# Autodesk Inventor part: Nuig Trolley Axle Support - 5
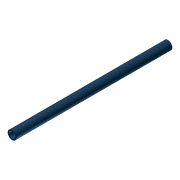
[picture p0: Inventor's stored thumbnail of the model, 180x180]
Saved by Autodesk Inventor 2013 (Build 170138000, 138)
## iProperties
Shininess: 64.0
Length Units: 11269
Angle Units: 11279
Time Units: 11290
Mass Units: 11286
Length Display Precision: 3
Angle Display Precision: 2
Created: 2002-08
Part Number: Nuig Trolley Axle Support - 5
Document SubType Name: Modeling
Designer: kalamea
Density: 1 g/cm^3
Material: Generic
Mass: 100.65 g
Surface Area: 638.451 cm^2
Volume: 100.65 cm^3
Density: 0.0
Volumn: 0.0
Area: 0.0
PropertySet Name: Model Information
Control State: 0
Master: False
Checked Out: False
DRAWING NUMBER: ME04-2007-PT
Author: kalamea
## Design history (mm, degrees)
sketch "Sketch1"
  geometry: C1 r 12.7 at (0, 0); C2 r 9.525 at (0, 0); 1 further point
  constraints: 2 centre point, 2 coincident
  dimensions: "d0" = 19.05 diameter of C2; "d1" = 25.4 diameter of C1
extrude "Extrusion1" new body sketch "Sketch1" stored distance "d2" = 454.025; taper "d3" = 0 deg
body "Solid1"
